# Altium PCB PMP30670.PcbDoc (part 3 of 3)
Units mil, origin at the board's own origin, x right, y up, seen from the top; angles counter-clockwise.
Board outline 5900 x 3950 mil, 4 copper layers (Top Layer, GND, Signal Layer, Bottom Layer), stack 79.834 mil thick; 198 components, 106 nets, 638 pads, 723 vias.
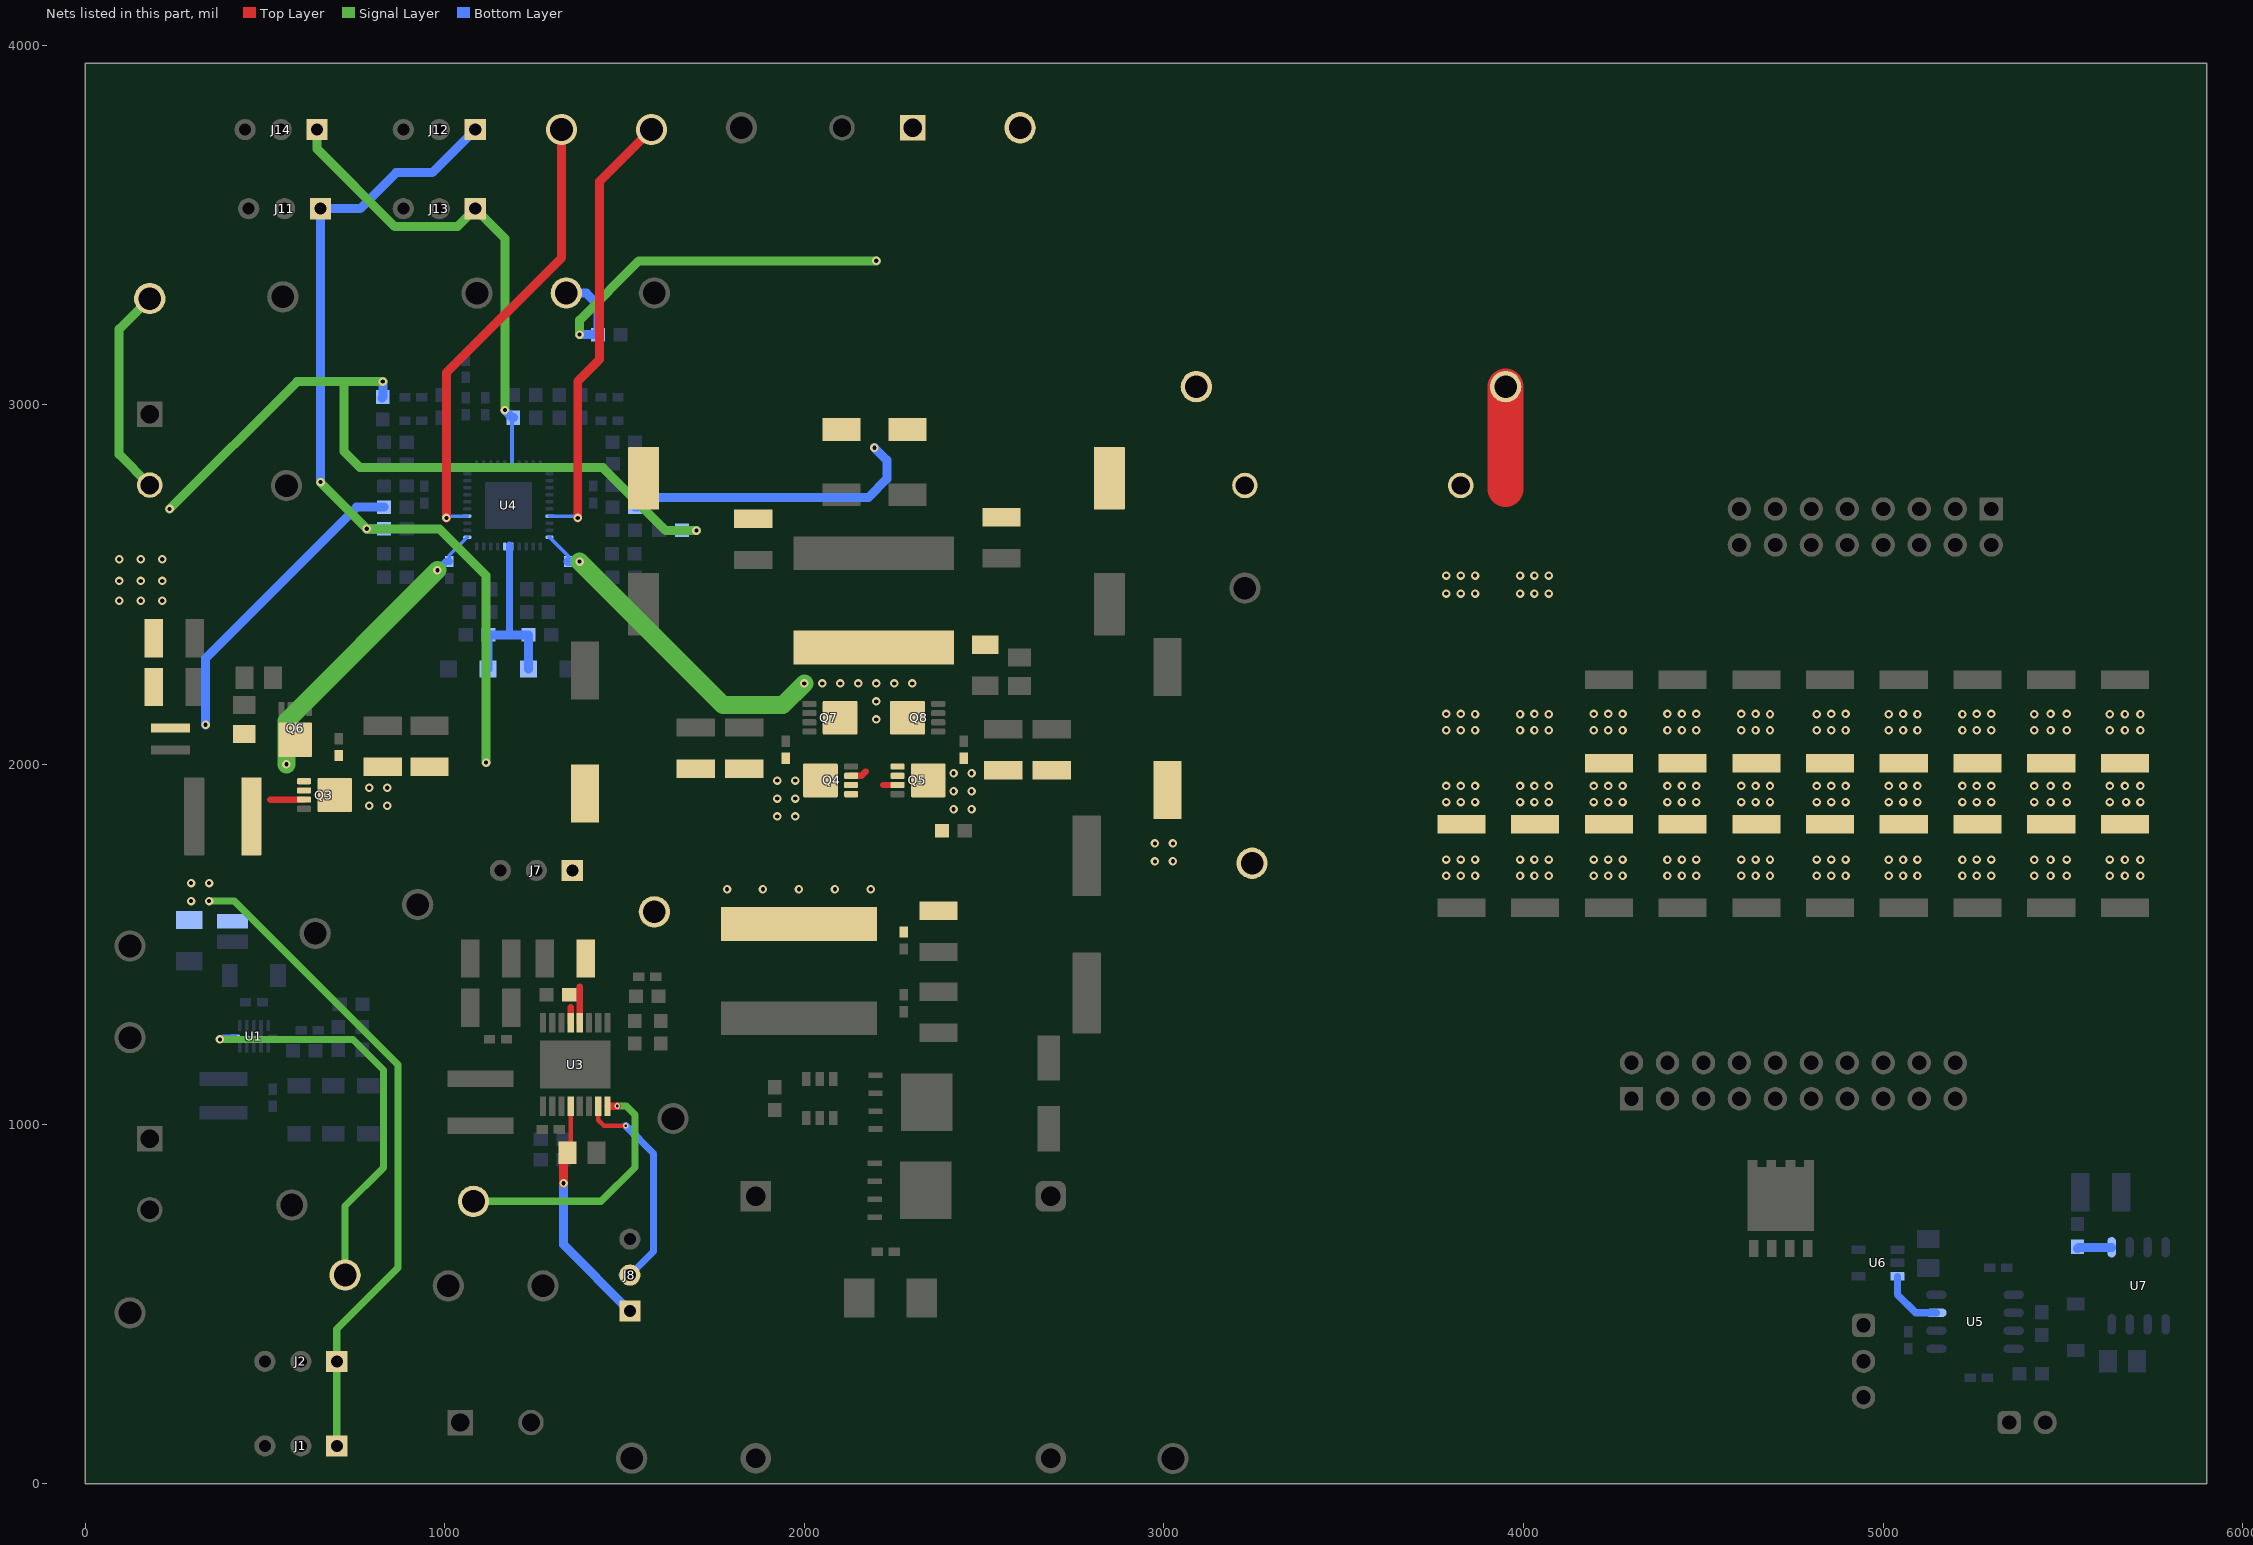
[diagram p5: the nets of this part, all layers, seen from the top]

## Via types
v1: diameter 23.62, hole 11.81, Top Layer to Bottom Layer, tented both sides, 701 vias
v2: diameter 23.62, hole 11.81, Top Layer to Bottom Layer, 11 vias
v3: diameter 15.75, hole 7.87, Top Layer to Bottom Layer, tented both sides, 7 vias
v4: diameter 196.85, hole 118.11, Top Layer to Bottom Layer, 4 vias

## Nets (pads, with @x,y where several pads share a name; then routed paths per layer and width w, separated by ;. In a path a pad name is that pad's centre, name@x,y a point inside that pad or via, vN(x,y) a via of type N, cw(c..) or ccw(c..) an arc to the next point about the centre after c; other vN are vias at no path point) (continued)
NetR40_2: R40.2 R41.2 R42.2 R43.2 R44.2 R45.2 R46.2 R47.2 R48.2 R49.2 R50.2 R51.2 R52.2 R53.2 R54.2 R55.2 R56.2 R57.2 R58.2 TP28.1 | length 285
  Top Layer w100: 3950,2765 TP28.1@3950,3050
  other v1: 3785,1690.42 3825,1690.42 3865,1690.42 3990,1690.42 4030,1690 4070,1690.42 4195,1690.42 4235,1690.42 4275,1690.42 4400,1690.42 4440,1690 4480,1690.42 4605,1690.42 4645,1690.42 4685,1690 4815,1690.42 4855,1690.42 4895,1690 5015,1690 5055,1690 5095,1690 5220,1690.42 5260,1690 5300,1690.42 5420,1690.42 5465,1690.42 5510,1690.42 5630,1690.42 5672,1690.42 5715,1690.42 3785,1735.42 3825,1735.42 3865,1735.42 3990,1735.42 4030,1735.42 4070,1735.42 4195,1735.42 4235,1735.42 4275,1735.42 4400,1735 4440,1735.42 4480,1735.42 4605,1735.42 4645,1735.42 4685,1735.42 4815,1735.42 4855,1735.42 4895,1735.42 5015,1735 5055,1735 5095,1735.42 5220,1735 5260,1735.42 5300,1735.42 5420,1735 5465,1735 5510,1735.42 5630,1735.42 5672,1735 5715,1735 3785,1895 3825,1895 3865,1895 3990,1895 4030,1895 4070,1895 4195,1895 4235,1895 4275,1895 4400,1895 4440,1895 4480,1895 4605,1895 4645,1895 4685,1895 4815,1895 4855,1895 4895,1895 5015,1895 5055,1895 5095,1895 5220,1895 5260,1895 5300,1895 5420,1895 5465,1895 5510,1895 5630,1895 5675,1895 5715,1895 3785,1940 3825,1940 3865,1940 3990,1940 4030,1940 4070,1940 4195,1940 4235,1940 4275,1940 4400,1940 4440,1940 4480,1940 4605,1940 4645,1940 4685,1940 4815,1940 4855,1940 4895,1940 5015,1940 5055,1940 5095,1940 5220,1940 5260,1940 5300,1940 5420,1940 5465,1940 5510,1940 5630,1940 5672,1940 5715,1940 3785,2095 3825,2095 3865,2095 3990,2095 4030,2095 4070,2095 4195,2095 4235,2095 4275,2095 4400,2095 4440,2095 4480,2095 4605,2095 4645,2095 4685,2095 4815,2095 4855,2095 4895,2095 5015,2095 5055,2095 5095,2095 5220,2095 5260,2095 5300,2095 5420,2095 5465,2095 5510,2095 5630,2095 5672,2095 5715,2095 3785,2140 3825,2140 3865,2139.58 3990,2139.58 4030,2140 4070,2139.58 4195,2140 4235,2140 4275,2140 4400,2140 4440,2140 4480,2140 4605,2140 4645,2140 4685,2139.58 4815,2139.58 4855,2140 4895,2140 5015,2139.58 5055,2140 5095,2139.58 5220,2139.58 5260,2140 5300,2140 5420,2139.58 5465,2140 5510,2140 5630,2139.58 5672,2139.58 5715,2139.58 3785,2475 3825,2475 3865,2475 3990,2475 4030,2475 4070,2475 3785,2525 3825,2525 3865,2525 3990,2525 4030,2525 4070,2525
NetR61_1: R61.1 U7.1 | length 96.6
  Bottom Layer w25: R61.1@5540,653.5 5543.78,657.28 U7.1@5635,657.28
NetTP5_1: TP5.1 U1.9 | length 1150.4
  Signal Layer w20: v1(375,1235) 745,1235 830,1150 830,878.62 723.19,771.81 TP5.1@723.19,580
  Bottom Layer w10: v1(375,1235) 383.46,1243.46 U1.9@417.48,1243.46
NetTP13_1: TP13.1 U3.8 | length 720.5
  Top Layer w20: U3.8@1453.78,1049.21 1479.21,1049.21 v3(1480,1050)
  Signal Layer w20: TP13.1@1080,785 1435,785 1529.07,879.07 1529.07,1025.93 1505,1050 v3(1480,1050)
NetTP21_1: TP21.1 U4.24 | length 1272.8
  Top Layer w25: v1(1005,2685) 1005,3088.89 1325,3408.89 TP21.1@1325,3765
  Bottom Layer w10: v1(1005,2685) 1010.35,2690.35 U4.24@1063.07,2690.35
NetTP22_1: TP22.1 U4.7 | length 1245.7
  Top Layer w25: v1(1370,2685) 1370,3065 1430,3125 1430,3620 TP22.1@1575,3765
  Bottom Layer w10: U4.7@1291.42,2690.35 1364.65,2690.35 v1(1370,2685)
NetU5_3: U5.3 U6.3 | length 180
  Bottom Layer w20: U6.3@5039.13,576.22 5039.13,525.87 5090,475 U5.3@5147.72,475
SW1: C47.2 L5.2 Q3.1 Q3.2 Q3.3 Q6.5 Q6.6 Q6.7 Q6.8 Q6.9@584.33,2068.62 R14.2 U4.21 | length 938.6
  Top Layer w18: 515.32,1901.89 Q3.3@609.02,1901.89
  Signal Layer w50: v1(560,2000) 560,2120 v1(980,2540)
  Bottom Layer w10: C47.2@1013.07,2563.98 1013.07,2581.22 U4.21@1063.07,2631.22
  Bottom Layer w20: v1(980,2540) 1003.98,2563.98 C47.2@1013.07,2563.98
SW2: C48.2 L6.1 Q4.1 Q4.2 Q4.3 Q5.1 Q5.2 Q5.3 Q7.5 Q7.6 Q7.7 Q7.8 Q7.9@2099.45,2129.68 Q8.5 Q8.6 Q8.7 Q8.8 Q8.9@2286.81,2129.69 R16.2 U4.10 | length 1020.7
  Top Layer w17.5: Q4.3@2130.16,1968.15 2158.91,1968.15 2170.76,1980 ; 2219.78,1942.64 Q5.3@2259.21,1942.64
  Signal Layer w50: v1(1375,2563.98) 1773.98,2165 1940,2165 v1(2000,2225)
  Bottom Layer w10: U4.10@1291.42,2631.3 1343.07,2579.65 C48.2@1343.07,2563.98
  Bottom Layer w25: C48.2@1343.07,2563.98 v1(1375,2563.98)
  other v1: 2200,2125 2200,2175 2050,2225 2100,2225 2150,2225 2200,2225 2250,2225 2300,2225
SYNC_3V3_BUCK: J8.2 U3.7 | length 620.6
  Top Layer w12: U3.7@1427.05,1049.21 1427.05,1010.67 1442.72,995 v3(1503.32,995)
  Bottom Layer w12: J8.2@1490,580 J8.2@1515,580
  Bottom Layer w20: v3(1503.32,995) 1580.69,917.63 1580.69,645.69 J8.2@1515,580
UBATT: C11.1 C14.1 C17.1 C18.1 C24.1 C25.1 C26.1 C27.1 C28.1 C29.1 C30.1 C31.1 C32.1 C33.1 C34.1 J7.1 J11.1 J12.1 L3.2 Q3.5 Q3.6 Q3.7 Q3.8 Q3.9@694.45,1914.68 Q4.5 Q4.6 Q4.7 Q4.8 Q4.9@2044.72,1955.35 Q5.5 Q5.6 Q5.7 Q5.8 Q5.9@2344.65,1955.43 R6.2 R18.1 TP9.1 TP15.1 U3.12 U3.13 | length 2563.1
  Top Layer w17.5: U3.13@1350.28,1281.5 1350.28,1325 ; U3.12@1375.87,1281.5 1375.87,1382.47
  Signal Layer w25: v1(655,2785) 655,2783.07 v1(783.07,2655) 985,2655 1115,2525 v1(1115,2005)
  Bottom Layer w25: v1(655,2785) J11.1@655,3545 765,3545 865,3645 965,3645 J12.1@1085,3765 ; v1(783.07,2655) 831.22,2655 R18.1@831.57,2655.35
  other v1: 1785,1652.66 1885,1652.66 1985,1652.66 2085,1652.66 2185,1652.66 2975,1730 3025,1730.42 2975,1780 3025,1780 1925,1855 1975,1855 2415,1875 2465,1875 790,1885 840,1885 1925,1905 1975,1905 2415,1925 2465,1925 790,1935 840,1935 1925,1955 1975,1955 2415,1975 2465,1975
VCC_3V3_SINGLE_BUCK: C23.1 J8.1 U3.4 | length 603.4
  Top Layer w12: C23.1@1350.28,937.21 U3.4@1350.28,1049.21
  Top Layer w25: v1(1330.68,835) C23.1@1330.68,895
  Bottom Layer w25: v1(1330.68,835) 1330.68,664.32 J8.1@1515,480
VCC_DUAL_BUCK: C45.1 C46.1 D2.2 D3.2 U4.15 U4.16 | length 552.4
  Bottom Layer w20: 1180,2360 1180,2610
  Bottom Layer w25: D2.2@1121.06,2265 1121.06,2359.57 C46.1@1121.49,2360 1180,2360 C45.1@1233.5,2360 1232.95,2359.45 D3.2@1232.95,2265
VDDA_DUAL_BUCK: C43.2 J13.1 J14.1 U4.36 | length 1361.6
  Signal Layer w25: J14.1@645,3765 645,3711.49 861.49,3495 1035,3495 J13.1@1085,3545 1167.4,3462.6 v1(1167.4,2985)
  Bottom Layer w10: U4.36@1187.09,2834.06 1187.09,2960.12 C43.2@1190.83,2963.86
  Bottom Layer w25: v1(1167.4,2985) 1188.54,2963.86 C43.2@1190.83,2963.86
VOUT1_DUAL_BUCK: C35.1 C36.1 J1.1 J2.1 J9.2 L1.1 R1.1 R12.1 R17.2 R29.1 R31.2 TP19.1 | length 5381
  Signal Layer w20: v1(345,1620) 415,1620 870,1165 870,600 700,430 J2.1@700,340 J1.1@700,105
  Signal Layer w25: J9.2@180,2776.57 95,2861.57 95,3210 TP19.1@180,3295 ; v1(235,2710) 589.41,3064.41 720,3064.41 ; v1(828.07,3064.41) 720,3064.41 ; v1(1700,2650) 1615,2650 1440,2825 765,2825 720,2870 720,3064.41
  Bottom Layer w25: v1(335,2110) 335,2295 755.35,2715.35 R29.1@831.57,2715.35 ; R31.2@825.2,3018.98 R31.2@828.07,3021.85 v1(828.07,3064.41) ; R17.2@1659.57,2650.35 1659.92,2650 v1(1700,2650)
  other v1: 295,1620 295,1670 345,1670 95,2455 155,2455 215,2455 95,2510 155,2510 215,2510 95,2570 155,2570 215,2570
VOUT2_DUAL_BUCK: C37.2 C38.1 C39.1 C41.2 J10.1 R13.2 R15.2 R30.2 R32.2 R40.1 TP17.1 TP20.1 TP27.1 | length 2002.8
  Signal Layer w25: v1(1375,3195) 1375,3235 1540,3400 v1(2200,3400)
  Bottom Layer w25: TP20.1@1338.07,3310.35 1394.1,3310.35 1426.1,3278.35 R32.2@1426.1,3195 v1(1375,3195) ; R30.2@1529.57,2715.35 1536.77,2715.35 1563.89,2742.48 2178.62,2742.48 2229.72,2793.59 2229.72,2845.63 v1(2195,2880.35)
pads on no net: Q3. Q3.9@681.65,1914.68 Q4. Q4.9@2057.52,1955.35 Q5. Q5.9@2331.85,1955.43 Q6. Q6.9@584.33,2081.42 Q7. Q7.9@2086.65,2129.68 Q8. Q8.9@2299.61,2129.69 U1.2@449.96,1218.86 U1.2@449.96,1268.07 U1.3@469.65,1218.86 U1.3@469.65,1268.07 U1.4@489.33,1218.86 U1.4@489.33,1268.07 U3.14 U3.17@1363.07,1165.35 U4.0 U4.39 U7.4 U7.5
copper on no net:
  other v4: 150,150 5750,150 150,3800 5750,3800

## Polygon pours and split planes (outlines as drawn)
SW2 on Bottom Layer "SW2_L04_P072" (solid, remove dead copper, pour order 72): 2165,1944.05 ccw(c2174.05,1944.05) 2174.05,1935 2265,1935 ccw(c2265,1950) 2280,1950 2280,2020 cw(c2295,2020) 2295,2035 2325,2035 ccw(c2325,2045) 2335,2045 2335,2245 cw(c2350,2245) 2350,2260 2530,2260 ccw(c2530,2275) 2545,2275 2545,2375 ccw(c2530.01,2375.01) 2530,2390 1980,2390 ccw(c1979.99,2375.01) 1965,2375 1965,2210 ccw(c1980,2210) 1980,2195 2035,2195 cw(c2035.01,2180.01) 2050,2180 2050,2065 ccw(c2065,2065) 2065,2050 2150,2050 cw(c2150.01,2035.01) 2165,2035
VOUT1_DUAL_BUCK on Bottom Layer "VOUT1_DUAL_BUCK_L04_P082" (solid, remove dead copper, pour order 82): 245,1540 245,1715 465,1715 465,1540
GND on Bottom Layer "GND_L04_P182" (solid, remove dead copper, pour order 182): 50,3100 50,3850 cw(c100,3850) 100,3900 5800,3900 cw(c5800,3850) 5850,3850 5850,100 cw(c5800,100) 5800,50 100,50 cw(c100,100) 50,100
no net on Bottom Layer "NONET_L04_P148" (solid, remove dead copper, pour order 148): 5330,310
NetC60_1 on Bottom Layer "NETC60_1_L04_P146" (solid, remove dead copper, pour order 146): 5270,390 5405,390 5405,270 5270,270
NetC60_1 on Bottom Layer "NETC60_1_L04_P142" (solid, remove dead copper, pour order 142): 5615,875 5615,655 5505,655 5420,655 5420,775 5520,875
3V3_SINGLE_BUCK on Bottom Layer "3V3_SINGLE_BUCK_L04_P136" (solid, remove dead copper, pour order 136): 845,1515 cw(c860,1515) 860,1530 1170,1530 1170,50 cw(c1155.01,49.99) 1155,35 860,35 cw(c860,50) 845,50
GND on Bottom Layer "GND_L04_P120" (solid, remove dead copper, pour order 120): 485,1070 745,1070 745,1275 485,1275
NetC5_1 on Bottom Layer "NETC5_1_L04_P118" (solid, remove dead copper, pour order 118): 465,1325 465,1525 245,1525 245,1415 345,1315 455,1315
1V1_SINGLE_BUCK on Bottom Layer "1V1_SINGLE_BUCK_L04_P112" (solid, remove dead copper, pour order 112): 100,1015 cw(c150,1015) 150,1065 775,1065 cw(c775,1015) 825,1015 825,770.69 cw(c775,770.69) 775,720.69 150,720.69 cw(c150,770.69) 100,770.69
NetL2_1 on Bottom Layer "NETL2_1_L04_P110" (solid, remove dead copper, pour order 110): 305,1149.65 cw(c315,1149.65) 315,1159.65 470.35,1159.65 cw(c470.35,1150) 480,1150 480,1105 cw(c470,1105) 470,1095 315,1095 cw(c315,1105) 305,1105
NetR40_2 on Bottom Layer "NETR40_2_L04_P100" (solid, remove dead copper, pour order 100): 3550,2500 cw(c3597.5,2502.5) 3595,2550 5749.15,2550 cw(c5749.15,2500) 5799.15,2500 5799.15,1299.15 cw(c5750,1299.15) 5750,1250 3600.17,1250 cw(c3600,1300) 3550,1300
GND on Top Layer "GND_L01_P186" (solid, remove dead copper, pour order 186): 50,2648 50,3900 1495,3900 1495,2648
no net on Top Layer "NONET_L01_P185" (solid, remove dead copper, pour order 185): 2500,680 2500,900 2800,900 2800,1075 2500,1075 2465,1110 2465,1330 2226.81,1330 2196.81,1360 1705.02,1360 1705.02,1190 1710.02,1185 2235,1185 2235,680
GND on Top Layer "GND_L01_P178" (solid, remove dead copper, pour order 178): 3250,2039.84 3250,2650 253.62,2650 252.72,2649.09 252.72,2040
UBATT on Top Layer "UBATT_L01_P174" (solid, remove dead copper, pour order 174): 645,2039.84 3250,2039.84 3250,1495 645,1495
SW2 on Top Layer "SW2_L01_P170" (solid, remove dead copper, pour order 170): 2110.11,1915.11 ccw(c2120.21,1915.11) 2120.21,1905 2165.21,1905 ccw(c2165.21,1914.79) 2175,1914.79 2175,1925 cw(c2185,1925) 2185,1935 2190,1935 2190,1974.79 2120.26,1974.79 ccw(c2120.26,1964.64) 2110.11,1964.63
VOUT2_DUAL_BUCK on Top Layer "VOUT2_DUAL_BUCK_L01_P168" (solid, remove dead copper, pour order 168): 1935,2650 1515,2650 cw(c1515,2700) 1465,2700 1465,3850 cw(c1515,3850) 1515,3900 3300,3900 cw(c3300,3850) 3350,3850 3350,2700 cw(c3300,2700) 3300,2650
SW2 on Top Layer "SW2_L01_P166" (solid, remove dead copper, pour order 166): 2165,1944.05 ccw(c2174.05,1944.05) 2174.05,1935 2265,1935 ccw(c2265,1950) 2280,1950 2280,2020 cw(c2295,2020) 2295,2035 2325,2035 ccw(c2325,2045) 2335,2045 2335,2245 cw(c2350,2245) 2350,2260 2530,2260 ccw(c2530,2275) 2545,2275 2545,2375 ccw(c2530.01,2375.01) 2530,2390 1980,2390 ccw(c1979.99,2375.01) 1965,2375 1965,2210 ccw(c1980,2210) 1980,2195 2035,2195 cw(c2035.01,2180.01) 2050,2180 2050,2065 ccw(c2065,2065) 2065,2050 2150,2050 cw(c2150.01,2035.01) 2165,2035
GND on Top Layer "GND_L01_P164" (solid, remove dead copper, pour order 164): 2235,20 3250,20 3250,1530 2248.98,1530 2248.98,1340 2475,1340 2475,670 2235,670
VOUT1_DUAL_BUCK on Top Layer "VOUT1_DUAL_BUCK_L01_P162" (solid, remove dead copper, pour order 162): 350,2095 cw(c335,2095) 335,2080 65,2080 cw(c65,2095) 50,2095 50,2840 cw(c65,2840) 65,2855 240,2855 cw(c240,2840) 255,2840 255,2155 ccw(c270,2155) 270,2140 334.71,2140 cw(c334.71,2124.71) 350,2124.71
CS2_DUAL_BUCK on Top Layer "CS2_DUAL_BUCK_L01_P158" (solid, remove dead copper, pour order 158): 1955,2805 cw(c1975,2805) 1975,2825 2415,2825 cw(c2415,2810) 2430,2810 2430,2540 cw(c2415,2540) 2415,2525 1970,2525 cw(c1970,2540) 1955,2540
NetC40_1 on Top Layer "NETC40_1_L01_P156" (solid, remove dead copper, pour order 156): 400,2265 cw(c415,2265) 415,2280 465,2280 cw(c465,2265) 480,2265 480,2150 cw(c465,2150) 465,2135 415,2135 cw(c415,2150) 400,2150
CS1_DUAL_BUCK on Top Layer "CS1_DUAL_BUCK_L01_P154" (solid, remove dead copper, pour order 154): 325,2060 65,2060 ccw(c65,2045) 50,2045 50,1745 ccw(c65,1745) 65,1730 325,1730 ccw(c325,1745) 340,1745 340,2045 ccw(c325,2045)
SW1 on Top Layer "SW1_L01_P152" (solid, remove dead copper, pour order 152): 395,2105 cw(c410,2105) 410,2120 620,2120 cw(c620,2105) 635,2105 629.82,1910.18 cw(c617.33,1912.49) 615,1900 530,1900 ccw(c530,1880) 510,1880 510,1745 cw(c495.01,1744.99) 495,1730 410,1730 cw(c410,1745) 395,1745
GND on Top Layer "GND_L01_P150" (solid, remove dead copper, pour order 150): 3550,1070 cw(c3600,1070) 3600,1120 5750,1120 cw(c5750,1070) 5800,1070 5800,99.21 cw(c5750,99.21) 5750,49.21 3600,49.21 cw(c3600,99.21) 3550,99.21
NetC8_1 on Top Layer "NETC8_1_L01_P134" (solid, remove dead copper, pour order 134): 1750,1165 2230,1165 2230,20 1443.07,20 1443.07,135 1707.52,135 1705,1165
3V3_SINGLE_BUCK on Top Layer "3V3_SINGLE_BUCK_L01_P132" (solid, remove dead copper, pour order 132): 1195,1155 1135,1155 1134.33,1530 925,1530 ccw(c925,1515) 910,1515 910,1110 ccw(c925,1110) 925,1095 1195,1095
KL30 on Top Layer "KL30_L01_P130" (solid, remove dead copper, pour order 130): 2500,680 2500,900 2800,900 2800,1075 2500,1075 2465,1110 2465,1330 2226.81,1330 2196.81,1360 1705.02,1360 1705.02,1190 1710.02,1185 2235,1185 2235,680
UBATT on Top Layer "UBATT_L01_P128" (solid, remove dead copper, pour order 128): 1325,1515 cw(c1340,1515) 1340,1530 1425,1530 cw(c1425,1515) 1440,1515 1440,1400 cw(c1425,1400) 1425,1385 1400,1385 ccw(c1400,1370) 1385,1370 1385,1251.97 1325,1251.97
GND on Top Layer "GND_L01_P126" (solid, remove dead copper, pour order 126): 1155,1516.33 cw(c1168.67,1516.33) 1168.67,1530 1295,1530 cw(c1295,1515) 1310,1515 1310,1090 1176.02,1090 cw(c1176.02,1111.02) 1155,1111.02
GND on Top Layer "GND_L01_P124" (solid, remove dead copper, pour order 124): 1690,845 cw(c1665,845) 1665,820 1400.03,820 cw(c1400.02,840) 1380.03,840 1380.03,1215 cw(c1400.02,1215) 1400.03,1235 1665,1235 cw(c1665,1210) 1690,1210
NetC16_2 on Top Layer "NETC16_2_L01_P122" (solid, remove dead copper, pour order 122): 995,1055 cw(c1020,1055) 1020,1080 1265,1080 cw(c1265,1055) 1290,1055 1290,985 cw(c1265,985) 1265,960 1020,960 cw(c1020,985) 995,985
GND on Top Layer "GND_L01_P114" (solid, remove dead copper, pour order 114): 490,1215 735.22,1215 735.22,1085.5 617.81,965 345,685 125,685 100,710 100,890
NetR40_2 on Top Layer "NETR40_2_L01_P086" (solid, remove dead copper, pour order 86): 3550,2110 3550,2800 cw(c3600,2800) 3600,2850 4100,2850 cw(c4100,2800) 4150,2800 4150,2110
GND on Top Layer "GND_L01_P098" (solid, remove dead copper, pour order 98): 3600,2563.98 cw(c3600,2613.98) 3550,2613.98 3550,3850 cw(c3600,3850) 3600,3900 5750,3900 cw(c5750,3850) 5800,3850 5800,2613.98 cw(c5750,2613.97) 5750,2563.98
NetJ15_1 on Top Layer "NETJ15_1_L01_P094" (solid, remove dead copper, pour order 94): 4000,1070 cw(c4050,1070) 4050,1120 5450,1120 cw(c5450,1070) 5500,1070 5500,745 cw(c5450,745) 5450,695 4050,695 cw(c4050,745) 4000,745
NetR40_2 on Top Layer "NETR40_2_L01_P088" (solid, remove dead copper, pour order 88): 3550,2125 cw(c3600,2125) 3600,2175 5750,2175 cw(c5750,2125) 5800,2125 5800,1700 cw(c5750,1700) 5750,1650 3600,1650 cw(c3600,1700) 3550,1700
UBATT on Signal Layer "UBATT_L03_P172" (solid, remove dead copper, pour order 172): 645,2039.84 3250,2039.84 3250,1495 645,1495
NetC8_1 on Signal Layer "NETC8_1_L03_P184" (solid, remove dead copper, pour order 184): 1750,1165 2230,1165 2230,20 1443.07,20 1443.07,135 1707.52,135 1705,1165
VOUT1_DUAL_BUCK on Signal Layer "VOUT1_DUAL_BUCK_L03_P176" (solid, remove dead copper, pour order 176): 50,2589.12 285,2589.12 285,1795 420,1660 420,1560 50,1560
GND on Signal Layer "GND_L03_P180" (solid, remove dead copper, pour order 180): 50,3850 cw(c100,3850) 100,3900 5800,3900 cw(c5800,3850) 5850,3850 5850,100 cw(c5800,99.99) 5800,50 100,49.21 cw(c100,99.21) 50,99.21
NetJ15_1 on Signal Layer "NETJ15_1_L03_P104" (solid, remove dead copper, pour order 104): 4000,1070 cw(c4050,1070) 4050,1120 5450,1120 cw(c5450,1070) 5500,1070 5500,745 cw(c5450,745) 5450,695 4050,695 cw(c4050,745) 4000,745
NetR40_2 on Signal Layer "NETR40_2_L03_P092" (solid, remove dead copper, pour order 92): 3550,2500 cw(c3597.5,2502.5) 3595,2550 5749.15,2550 cw(c5749.15,2500) 5799.15,2500 5799.15,1299.15 cw(c5750,1299.15) 5750,1250 3600.17,1250 cw(c3600,1300) 3550,1300
SW2 on GND "SW2_L02_P096" (solid, remove dead copper, pour order 96): 2165,1944.05 ccw(c2174.05,1944.05) 2174.05,1935 2265,1935 ccw(c2265,1950) 2280,1950 2280,2020 cw(c2295,2020) 2295,2035 2325,2035 ccw(c2325,2045) 2335,2045 2335,2245 cw(c2350,2245) 2350,2260 2530,2260 ccw(c2530,2275) 2545,2275 2545,2375 ccw(c2530.01,2375.01) 2530,2390 1980,2390 ccw(c1979.99,2375.01) 1965,2375 1965,2210 ccw(c1980,2210) 1980,2195 2035,2195 cw(c2035.01,2180.01) 2050,2180 2050,2065 ccw(c2065,2065) 2065,2050 2150,2050 cw(c2150.01,2035.01) 2165,2035
GND on GND "GND_L02_P106" (solid, remove dead copper, pour order 106): 100,50 cw(c100,100) 50,100 50,3850 cw(c100,3850) 100,3900 5750,3900 cw(c5750,3850) 5800,3850 5800,100 cw(c5750,99.99) 5750,50
NetJ15_1 on GND "NETJ15_1_L02_P102" (solid, remove dead copper, pour order 102): 4000,1070 cw(c4050,1070) 4050,1120 5450,1120 cw(c5450,1070) 5500,1070 5500,745 cw(c5450,745) 5450,695 4050,695 cw(c4050,745) 4000,745
NetR40_2 on GND "NETR40_2_L02_P090" (solid, remove dead copper, pour order 90): 3550,2500 cw(c3597.5,2502.5) 3595,2550 5749.15,2550 cw(c5749.15,2500) 5799.15,2500 5799.15,1299.15 cw(c5750,1299.15) 5750,1250 3600.17,1250 cw(c3600,1300) 3550,1300
no net on Top Overlay "NONET_L-01_P-001" (solid, pour order 74): 3995,53.12 3995,136.88 4078.75,136.88 4078.75,53.12

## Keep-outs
Keep-Out Layer:
  text ".Layer_Name" at 577,-858.49 h60

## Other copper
Top Layer:
  pour cut-out: 355,2150 395,2150 395,2080 355,2080
  pour cut-out: 1956.93,2390 1956.76,2525 2429.29,2525 2429.29,2390
  text ".Layer_Name" at 577,-858.49 h60
GND:
  pour cut-out: 305,1065.49 305,1095 480.29,1095 480.29,1065.49
  pour cut-out: 340.44,1722.28 338.75,1988.43 395,1988.43 395,1722.28
  pour cut-out: 835,0 833.47,1530 838.47,1530 840,0
  pour cut-out: 1956.93,2390 1956.76,2525 2429.29,2525 2429.29,2390
  pour cut-out: 1705.02,1495 1700,1495 1700,0 1705.02,0
Signal Layer:
  pour cut-out: 340.44,1722.28 338.75,1988.43 395,1988.43 395,1722.28
  pour cut-out: 1957.5,1935 1956.76,2525 2429.29,2525 2429.29,1935
  pour cut-out: 835,0 833.5,1495 838.5,1495 840,0
  pour cut-out: 1705.02,1495 1700,1495 1700,135 1705.02,135
Bottom Layer:
  pour cut-out: 340.44,1722.28 338.75,1988.43 395,1988.43 395,1722.28
  pour cut-out: 835,0 833.47,1529.82 838.47,1529.82 840,0
  pour cut-out: 255,1064.65 255,980 506.06,980 506.06,975 250,975 250,1064.65
  pour cut-out: 1956.93,2390 1956.76,2525 2429.29,2525 2429.29,2390
  pour cut-out: 1705.02,1495 1700,1495 1700,0 1705.02,0
  text ".Layer_Name" at 577,-858.49 h60

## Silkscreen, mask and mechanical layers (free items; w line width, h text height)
Top Overlay:
  text "-" at 1945,3855 h72.83
  text "+" at 2440,3846.98 h72.83
  text "-" at 125,3095.98 h72.83
  text "+" at 125,2600.98 h72.83
  text "Electronic Load: 5 A cont. (J16) + 10 A pulsed (J15)" at 3590,2430 h31.5 r270
  text "+" at 120.94,1080.47 h72.83
  text "-" at 120,580 h72.83
  text "PMP30670 Rev" at 3595,75 h31.5
  text "+" at 865,60.98 h72.83
  text "-" at 1375,60.98 h72.83
  text "IN+" at 2070,55 h72.83
  text "IN-" at 2410,55 h72.83
  text ".Layer_Name" at 577,-858.49 h60
Bottom Overlay:
  text ".Layer_Name" at 577,-858.49 h60
Top Paste:
  text ".Layer_Name" at 577,-858.49 h60
Bottom Paste:
  text ".Layer_Name" at 577,-858.49 h60
Top Solder:
  text ".Layer_Name" at 577,-858.49 h60
  text ".Layer_Name" at 577,-858.49 h60
Bottom Solder:
  text ".Layer_Name" at 577,-858.49 h60
Drill Guide:
  text ".Layer_Name" at 577,-858.49 h60
M1 Board Outline:
  the board outline again, w19.68
  text ".Layer_Name" at 577,-858.49 h60
M2 Board Dimensions:
  rectangle: 125,-400 500,-275
  rectangle: 0,-275 125,-150
  lines w7: 0,-275 1000,-275 ; 125,-400 125,-150 ; 250,-400 250,-150 ; 500,-400 500,-150 ; 750,-400 750,-150 ; 0,-400 0,-150 1000,-150 1000,-400 0,-400
  text "PMP30670" at 55,4035 h72.83
  text ".Layer_Name" at 577,-858.49 h60
M3 3D STEP Top:
  text ".Layer_Name" at 577,-858.49 h60
M4 3D STEP Bottom:
  text ".Layer_Name" at 577,-858.49 h60
M5 Assembly Top:
  lines w10: -292,-930.17 6308,-930.17 ; -292,-726.83 6310,-726.83 ; -292,-523.5 -292,-1133.5 3713,-1133.5 6310,-1133.5 6310,-523.5 -291.5,-523.5 -291.5,-1133.5 1284,-1133.5 ; 2173,-1133.5 2173,-523.5 ; 3440,-726.83 3440,-523.5 ; 4280,-726.83 4280,-523.5 ; 4902,-1140 4902,-937.17
  text "COMPONENTS MARKED 'DNP' SHOULD NOT BE POPULATED." at 1153.5,-318.5 h60
  text "ASSEMBLY VARIANT:" at 1153,-434 h60
  text ".VariantName" at 2189,-434 h60
  text "PCB VIEWED FROM TOP SIDE" at -228.5,-655.67 h60
  text "BOARD #:" at 2248,-655.67 h60
  text ".PRJ_Number" at 2793.5,-655.67 h60
  text "REV:" at 3638,-655.67 h60
  text ".PCB_Rev" at 3929.5,-655.67 h60
  text "SVN REV:" at 4476,-655.67 h60
  text ".VersionControl_RevNumber" at 4982,-655.67 h60
  text "TID #:" at 2248,-859 h60
  text ".TID" at 2793.5,-859 h60
  text "PLOT NAME =" at -228.5,-1064.34 h60
  text ".plot_File_Name" at 577,-1064.34 h60
  text "GENERATED    :" at 2250,-1064.34 h60
  text ".Print_Date" at 3119.5,-1064.34 h60
  text ".Print_Time" at 3848.5,-1064.34 h60
  text "TEXAS INSTRUMENTS" at 5113,-1064.34 h60
M6 Assembly Bottom:
  lines w10: -292.5,-727.33 6309.5,-727.33 ; -290.5,-930.67 6309.5,-930.67 ; 1115.5,-1140.5 1115.5,-937.67 ; 1737.5,-727.33 1737.5,-524 ; 2577.5,-727.33 2577.5,-524 ; 3844.5,-1134 3844.5,-524 ; 4733.5,-1134 6309,-1134 6309,-524 -292.5,-524 -292.5,-1134 2304.5,-1134 6309.5,-1134 6309.5,-524
  text "COMPONENTS MARKED 'DNP' SHOULD NOT BE POPULATED." at 6102,-318 h60
  text ".VariantName" at 5058,-434 h60
  text "ASSEMBLY VARIANT:" at 6097,-434 h60
  text ".VersionControl_RevNumber" at 1035.5,-656.17 h60
  text "SVN REV:" at 1541.5,-656.17 h60
  text ".PCB_Rev" at 2088,-656.17 h60
  text "REV:" at 2379.5,-656.17 h60
  text ".PRJ_Number" at 3224,-656.17 h60
  text "BOARD #:" at 3769.5,-656.17 h60
  text "PCB VIEWED FROM BOTTOM SIDE" at 6246,-656.17 h60
  text ".TID" at 3224,-859.5 h60
  text "TID #:" at 3769.5,-859.5 h60
  text "TEXAS INSTRUMENTS" at 904.5,-1064.84 h60
  text ".Print_Time" at 2169,-1064.84 h60
  text ".Print_Date" at 2898,-1064.84 h60
  text "GENERATED    :" at 3767.5,-1064.84 h60
  text ".plot_File_Name" at 5440.5,-1064.84 h60
  text "PLOT NAME =" at 6246,-1064.84 h60
M9 Title Sheet:
  drawing of 57 lines, arcs and shapes, not listed
  text "1" at 739.84,8036.5 h70
  text "2" at 3235.5,8036.5 h70
  text "3" at 5724.84,8036.5 h70
  text "4" at 8231.51,8036.5 h70
  text "5" at 10730.5,8036.5 h70
  text "6" at 13235.5,8036.5 h70
  text "A" at -416.5,6893.5 h70
  text "A" at 14383.5,6893.5 h70
  text "B" at -416.5,4513.5 h70
  text "B" at 14383.5,4513.5 h70
  text "C" at -416.5,2138.5 h70
  text "C" at 14383.5,2138.5 h70
  text "PROJECT TITLE:" at 11343.5,277.5 h45
  text ".PRJ_Title" at 11393.5,144.17 h70
  text "DESIGNED FOR:" at 11343.5,-23.5 h45
  text ".PRJ_Customer" at 11393.5,-163.5 h70
  text "D" at -416.5,-231.5 h70
  text "D" at 14383.5,-231.5 h70
  text "FILE NAME:" at 11343.5,-323.5 h45
  text ".PCB_File_Name_No_Path" at 11393.5,-443.5 h70
  text "Texas Instruments (TI) and/or its licensors do not warrant the accuracy or completeness of this specification" at 6374,-605.34 h45
  text "ENGINEER:" at 11343.5,-613.5 h45
  text "LAYOUT BY:" at 12848.5,-613.5 h45
  text "or any information contained therein. TI and/or its licensors do not warrant that this design will meet" at 6329.01,-718 h45
  text ".PRJ_Engineer" at 11393.5,-768.49 h70
  text ".PCB_Layout" at 12899,-768.49 h70
  text "the specifications, will be suitable for your application or fit for any particular purpose, or will operate in" at 6329.01,-830.67 h45
  text ".Layer_Name" at 577,-858.49 h60
  text "ALTIUM DESIGNER VERSION:" at 12848.5,-923.5 h45
  text "an implementation. TI and/or its licensors do not warrant that the design is production worthy. You should" at 6329.01,-943.33 h45
  text "completely validate and test your design implementation to confirm the system functionality for your application." at 6374,-1056 h45
  text ".print_Scale" at 11393.5,-1056.83 h70
  text ".Application_BuildNumber" at 12899,-1056.83 h70
  text "1" at 739.84,-1263.5 h70
  text "2" at 3235.5,-1263.5 h70
  text "3" at 5724.84,-1263.5 h70
  text "4" at 8231.51,-1263.5 h70
  text "5" at 10730.5,-1263.5 h70
  text "6" at 13235.5,-1263.5 h70
M10 Fab Notes:
  drawing of 173 lines, arcs and shapes, not listed
  text "DESIGN INFORMATION" at 12377.02,6201 h60
  text "MIN. TRACK WIDTH:" at 11732.46,6021 h60
  text "8" at 12828.7,6021 h60
  text "MIL" at 12983.46,6021 h60
  text "MIN. CLEARANCE:" at 11732.46,5889 h60
  text "0.2" at 12768.7,5889 h60
  text "mm" at 12983.46,5889 h60
  text "MIN. VIA PAD SIZE:" at 11732.46,5757 h60
  text "24" at 12798.71,5757 h60
  text "MIL" at 12983.46,5757 h60
  text "0.05mm (2MIL)" at 12427.46,5615.29 h60
  text "MINIMUM ANNULAR RING" at 11403.23,5611 h60
  text "EXTERNAL" at 13135.46,5611 h60
  text "PER" at 11603.23,5493 h60
  text "IPC-D-275 CLASS 2 LEVEL C" at 11823.23,5493 h60
  text "MIL, HOLES" at 13311.46,5380.71 h60
  text "+/-" at 12919,5380 h60
  text "+/-" at 13773,5380 h60
  text "REGISTRATION TOLERANCES:" at 11403.23,5375 h60
  text "METAL" at 12603,5375 h60
  text "5" at 13179.2,5375 h60
  text "3" at 14012.2,5375 h60
  text "MIL" at 14128.46,5375 h60
  text "+/-" at 13773,5262 h60
  text "HOLE SIZE TOLERANCE (UNLESS OTHERWISE SPECIFIED):" at 11403.23,5257 h60
  text "3" at 14012.2,5257 h60
  text "MIL" at 14128.46,5257 h60
  text "MATERIAL:" at 11328.46,5047.54 h60
  text "FR-4 High Tg" at 12314.9,4907.21 h60
  text "FR-408" at 11749.46,4898.64 h60
  text "OTHER" at 13237.46,4898.64 h60
  text "X" at 12160,4895 h60
  text "62 MIL (1.6mm) +/-10%" at 12069.56,4735.92 h60
  text "THICKNESS:" at 11403.23,4731.64 h60
  text "X" at 11941.4,4731.64 h60
  text "OTHER" at 13354.46,4731.64 h60
  text "TOLERANCE:" at 11403.23,4573.64 h60
  text "X" at 12242.53,4573.64 h60
  text "ANSI IPC-6012 TYPE 3 CLASS 2" at 12429.48,4573.64 h60
  text "OTHER +/-" at 12429.46,4417.64 h60
  text "BOW & TWIST:" at 11403.23,4260.64 h60
  text "X" at 12242.53,4260.64 h60
  text "ANSI IPC-6012 TYPE 3 CLASS 2" at 12429.48,4260.64 h60
  text "OTHER +/-" at 12429.46,4102.13 h60
  text "DRILLING:" at 11328.46,3963.64 h60
  text "REFERENCE:" at 11403.23,3846.64 h60
  text "X" at 12051.46,3846.64 h60
  text "AS SHOWN" at 12238.46,3846.64 h60
  text "X" at 12952.46,3846.64 h60
  text "NC_DRILL FILES" at 13089.46,3846.64 h60
  text "PTH COPPER THICKNESS:" at 11403.23,3688.64 h60
  text "X" at 12533.46,3688.64 h60
  text "20-30 um" at 12670.46,3688.64 h60
  text "OTHER" at 13387.46,3688.64 h60
  text "BOARD FINISH:" at 11328.46,3529.64 h60
  text "SILKSCREEN:" at 11483.68,3411.64 h60
  text "X" at 12432.46,3411.64 h60
  text "TOP" at 12558.46,3411.64 h60
  text "X" at 12942.46,3411.64 h60
  text "BOTTOM" at 13069.46,3411.64 h60
  text "SILKSCREEN COLOR:" at 11483.68,3244.64 h60
  text "X" at 12431.42,3244.64 h60
  text "WHITE" at 12558.46,3244.64 h60
  text "OTHER" at 13069.46,3244.64 h60
  text "X" at 12562.42,3085.44 h60
  text "GREEN" at 12689.46,3085.44 h60
  text "OTHER" at 13307.46,3085.44 h60
  text "SOLDER RESIST COLOR:" at 11483.68,3074.64 h60
  text "X" at 12562.42,2915.44 h60
  text "MATTE" at 12689.46,2915.44 h60
  text "SEMI-GLOSS" at 13307,2914.8 h60
  text "IMMERSION GOLD (ENIG)" at 12389.46,2726.92 h60
  text "ENEPIG" at 13727,2723.64 h60
  text "SURFACE FINISH:" at 11328.46,2722.64 h60
  text "X" at 12202.51,2722.64 h60
  text "IMM. TIN/SILVER OR EQUIV" at 11658,2565.64 h60
  text "OTHER" at 13089.46,2565.64 h60
  text "ARRAY/PANEL:" at 11328.46,2386.64 h60
  text "CUT AND TRIM PER M1 BOARD OUTLINE" at 12389.46,2382.35 h60
  text "N.C. ROUTE" at 12389.46,2230.64 h60
  text "X" at 13068.46,2230.64 h60
  text "V. SCORE" at 13255.46,2230.64 h60
  text "CERTIFICATION:" at 11328.46,2093.64 h60
  text "MATERIALS AND WORKMANSHIP FOR ALL PCBS" at 12053.46,2093.64 h60
  text "TO MEET OR EXCEED THE REQUIREMENTS OF:" at 12053.46,1995.64 h60
  text "X" at 11679.96,1859.13 h60
  text "ANSI IPC-A-600F CLASS ->" at 11818.96,1859.13 h60
  text "X" at 13458.02,1859.13 h60
  text "2" at 13576.96,1859.14 h60
  text "1" at 13261.96,1857.64 h60
  text "3" at 13930.96,1857.64 h60
  text "X" at 12494.02,1699.64 h60
  text "RoHS" at 12630.96,1699.64 h60
  text "OTHER" at 13275.36,1699.64 h60
  text "PER ORDER" at 13672.42,1699.64 h60
  text "ALL BOARDS MUST MEET OR EXCEED UL94-V0 REQUIREMENTS." at 11356,1534 h60
  text "PCB MUST BEAR THE UL94V-0 UL REGISTERED MATERIAL ID NUMBER" at 11356,1414 h60
  text "ADDITIONAL REQUIREMENTS:" at 11328.46,1240.64 h60
  text "MICROSECTION:" at 11403.23,1125.64 h60
  text "YES" at 12308.96,1125.64 h60
  text "REQUIRED" at 13170.46,969.49 h60
  text "BARE BOARD ELEC. TEST:" at 11403.23,966.64 h60
  text "NONE" at 12708.96,966.64 h60
  text "X" at 13043.46,966.64 h60
  text "PER ORDER" at 13762.46,966.64 h60
  text ".Layer_Name" at 577,-858.49 h60
M11 Gerber Information:
  lines w10: -292,-930.17 6308,-930.17 ; -292,-726.83 6310,-726.83 ; -292,-523.5 -292,-1133.5 3713,-1133.5 6310,-1133.5 6310,-523.5 -291.5,-523.5 -291.5,-1133.5 1284,-1133.5 ; 2173,-1133.5 2173,-523.5 ; 3440,-726.83 3440,-523.5 ; 4280,-726.83 4280,-523.5 ; 4902,-1140 4902,-937.17
  text "ALL ARTWORK VIEWED FROM TOP SIDE" at -228.5,-655.67 h60
  text "BOARD #:" at 2248,-655.67 h60
  text ".PRJ_Number" at 2793.5,-655.67 h60
  text "REV:" at 3638,-655.67 h60
  text ".PCB_Rev" at 3929.5,-655.67 h60
  text "SVN REV:" at 4476,-655.67 h60
  text ".VersionControl_RevNumber" at 4982,-655.67 h60
  text "LAYER NAME =" at -228.5,-858.49 h60
  text "TID #:" at 2248,-859 h60
  text ".TID" at 2793.5,-859 h60
  text "PLOT NAME =" at -228.5,-1064.34 h60
  text ".plot_File_Name" at 577,-1064.34 h60
  text "GENERATED    :" at 2250,-1064.34 h60
  text ".Print_Date" at 3119.5,-1064.34 h60
  text ".Print_Time" at 3848.5,-1064.34 h60
  text "TEXAS INSTRUMENTS" at 5113,-1064.34 h60
M12 Stackup:
  drawing of 295 lines, arcs and shapes, not listed
  text "Layer" at 9798.08,7335 h60
  text "Name" at 10207.99,7335 h60
  text "Material" at 11137.73,7335 h60
  text "Thickness" at 11997.5,7335 h60
  text "Constant" at 12647.34,7335 h60
  text "Board Layer Stack" at 13217.2,7335 h60
  text "1" at 9798.08,7215 h60
  text "Top Overlay" at 10207.99,7215 h60
  text "2" at 9798.08,7095 h60
  text "Top Solder" at 10207.99,7095 h60
  text "Solder Resist" at 11137.73,7095 h60
  text "0.40mil" at 11997.5,7095 h60
  text "3.5" at 12647.34,7095 h60
  text "3" at 9798.08,6975 h60
  text "Top Layer" at 10207.99,6975 h60
  text "Copper" at 11137.73,6975 h60
  text "1.40mil" at 11997.5,6975 h60
  text "4" at 9798.08,6855 h60
  text "Dielectric1" at 10207.99,6855 h60
  text "FR-4" at 11137.73,6855 h60
  text "59.20mil" at 11997.5,6855 h60
  text "4.8" at 12647.34,6855 h60
  text "5" at 9798.08,6735 h60
  text "GND" at 10207.99,6735 h60
  text "Copper" at 11137.73,6735 h60
  text "1.42mil" at 11997.5,6735 h60
  text "6" at 9798.08,6615 h60
  text "Dielectric 3" at 10207.99,6615 h60
  text "5.00mil" at 11997.5,6615 h60
  text "4.2" at 12647.34,6615 h60
  text "7" at 9798.08,6495 h60
  text "Signal Layer" at 10207.99,6495 h60
  text "Copper" at 11137.73,6495 h60
  text "1.42mil" at 11997.5,6495 h60
  text "8" at 9798.08,6375 h60
  text "Dielectric 2" at 10207.99,6375 h60
  text "10.00mil" at 11997.5,6375 h60
  text "4.2" at 12647.34,6375 h60
  text "9" at 9798.08,6255 h60
  text "Bottom Layer" at 10207.99,6255 h60
  text "Copper" at 11137.73,6255 h60
  text "1.40mil" at 11997.5,6255 h60
  text "10" at 9798.08,6135 h60
  text "Bottom Solder" at 10207.99,6135 h60
  text "Solder Resist" at 11137.73,6135 h60
  text "0.40mil" at 11997.5,6135 h60
  text "3.5" at 12647.34,6135 h60
  text "11" at 9798.08,6015 h60
  text "Bottom Overlay" at 10207.99,6015 h60
  text ".Layer_Name" at 577,-858.49 h60
M13 Component Bodies Top:
  text ".Layer_Name" at 577,-858.49 h60
M14 Component Bodies Bottom:
  text ".Layer_Name" at 577,-858.49 h60
M15 Courtyards Top:
  text ".Layer_Name" at 577,-858.49 h60
M16 Courtyards Bottom:
  text ".Layer_Name" at 577,-858.49 h60
Drill Drawing:
  text ".Layer_Name" at 577,-858.49 h60

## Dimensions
0,0 to 5900,0 on M2 Board Dimensions
0,-400 to 1000,-400 on M2 Board Dimensions
0,0 to 0,3950 on M2 Board Dimensions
